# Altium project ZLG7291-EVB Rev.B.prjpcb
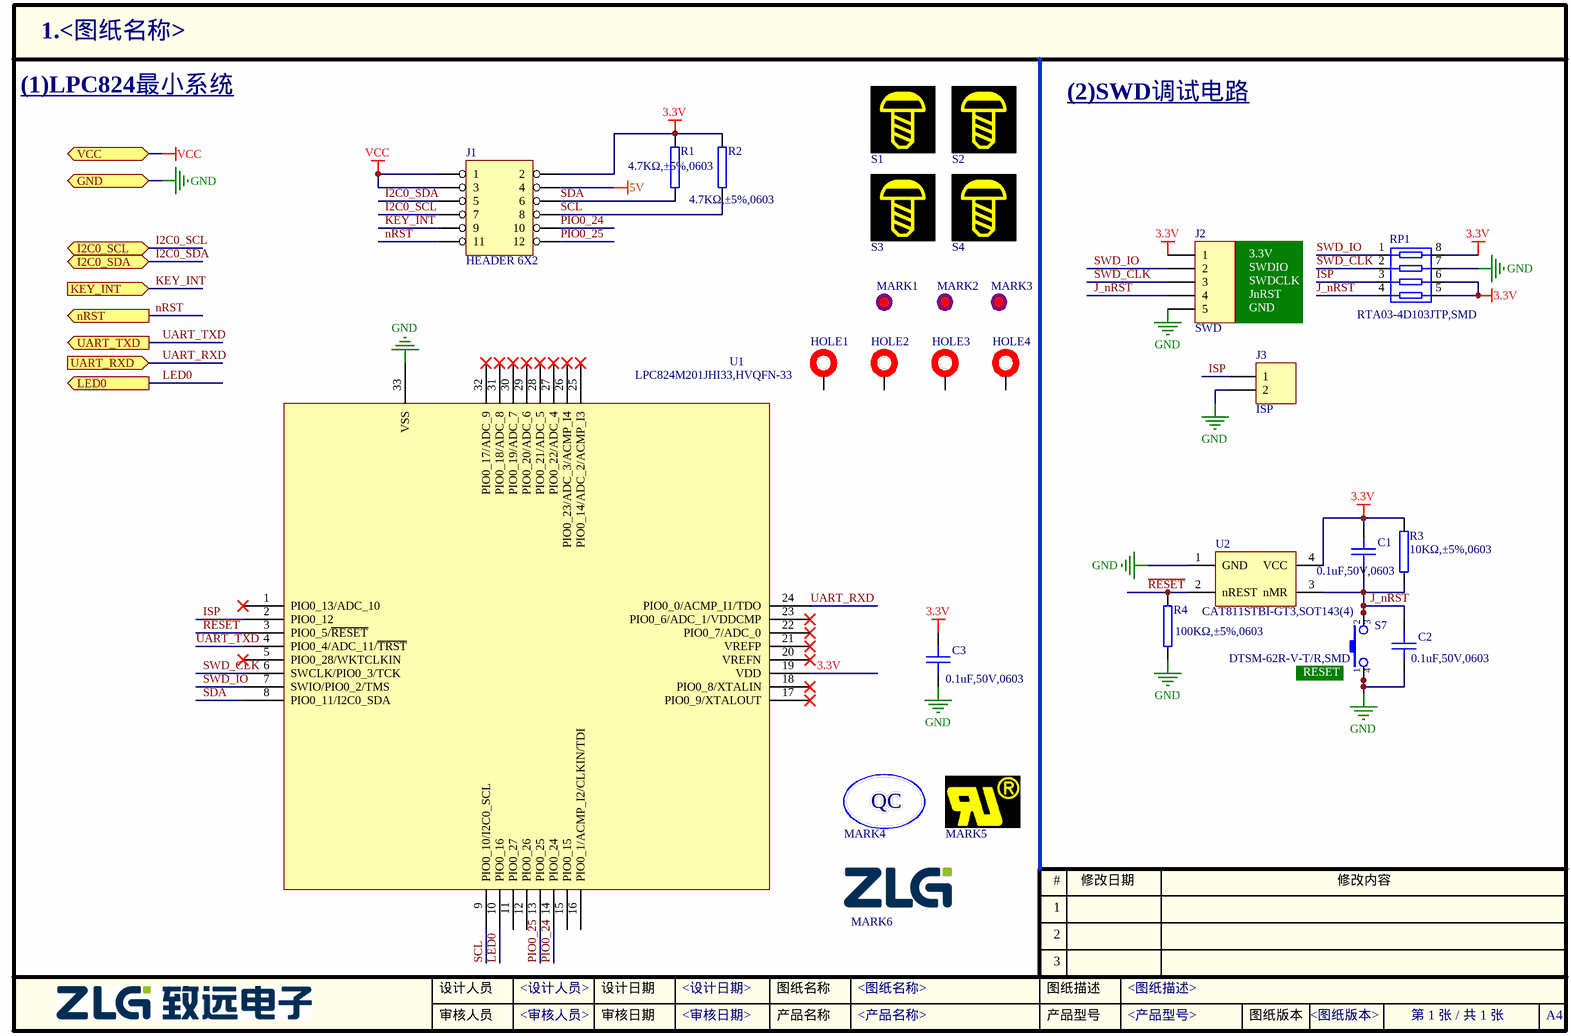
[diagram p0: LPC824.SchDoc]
3 sheets, 77 parts. Net scope: flat (ports and power ports of the same name join across sheets).
Board file: ZLG7291-EVB Rev.B.PCBDOC
Sheets:
  LPC824.SchDoc
  ZLG7291.SchDoc
  POWER.SchDoc

## Sheet LPC824.SchDoc
size A4; CheckedBy: <审核人员>; Author: <设计人员>; DocumentNumber: 1; SheetNumber: 1; SheetTotal: 1; PageSetup: Record=PageOptions|CenterHorizontal=True|CenterVertical=True|PrintScale=1.00|XCorrection=1.00|YCorrection=1.00|PrintKind=0|BorderSize=5000000|LeftOffset=0|BottomOffset=0|Orientation=2|PaperLength=1000|PaperWidth=1000|Scale=100|PaperSource=7|PrintQuality=600|MediaType=1|DitherType=10|PaperKind=A4|PrintScaleMode=1; DesignDate: <设计日期>; CheckDate: <审核日期>; SheetName: <图纸名称>; SheetVersion: <图纸版本>; SheetDescription: <图纸描述>; ProductName: <产品名称>; ProductModel: <产品型号>

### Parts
C1  0.1uF,50V,0603  [0603C]
C2  0.1uF,50V,0603  [0603C]
C3  0.1uF,50V,0603  [0603C]
HOLE1  HOLE - 不上螺丝  [HOLE-2.2]  (value not drawn)  (no BOM)
HOLE2  HOLE - 不上螺丝  [HOLE-2.2]  (value not drawn)  (no BOM)
HOLE3  HOLE - 不上螺丝  [HOLE-2.2]  (value not drawn)  (no BOM)
HOLE4  HOLE - 不上螺丝  [HOLE-2.2]  (value not drawn)  (no BOM)
J1  HEADER 6X2  [IDC-12-2.54]
J2  SWD  [SIP-5-2.54]
J3  ISP  [SIP-2-2.54]
MARK1  MARKER  [MARKER-C-1.0M]  (value not drawn)  (no BOM)
MARK2  MARKER  [MARKER-C-1.0M]  (value not drawn)  (no BOM)
MARK3  MARKER  [MARKER-C-1.0M]  (value not drawn)  (no BOM)
MARK4  ZY QC  [ZY_QC]  (value not drawn)  (no BOM)
MARK5  UR  [ZY_UR-3X2]  (value not drawn)  (no BOM)
MARK6  ZLGLOGO  [ZLG0.5]  (value not drawn)  (no BOM)
R1  4.7KΩ,±5%,0603  [0603R]
R2  4.7KΩ,±5%,0603  [0603R]
R3  10KΩ,±5%,0603  [0603R]
R4  100KΩ,±5%,0603  [0603R]
RP1  RTA03-4D103JTP,SMD  [0603RA]
S1  (no value)  [Screw-Mark2]  (no BOM)
S2  (no value)  [Screw-Mark2]  (no BOM)
S3  (no value)  [Screw-Mark2]  (no BOM)
S4  (no value)  [Screw-Mark2]  (no BOM)
S7  DTSM-62R-V-T/R,SMD  [KEY-6S]
U1  LPC824M201JHI33,HVQFN-33  [QFN50P500X500X85-33N]
U2  CAT811STBI-GT3,SOT143(4)  [SOT-143]

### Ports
GND, I2C0_SCL (bidir), I2C0_SDA (bidir), KEY_INT (in), LED0 (out), nRST (out), UART_RXD (in), UART_TXD (out), VCC

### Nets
3.3V: C1.1 C3.1 J1.2 J2.1 R1.2 R2.2 R3.2 RP1.5 RP1.6 RP1.8 U1.19(VDD) U2.4(VCC)
5V: J1.4
GND: C2.2 C3.2 J2.5 J3.2 R4.1 RP1.7 S7.1 S7.4 U1.33(VSS) U2.1(GND) ; port GND
VCC: J1.1 J1.3 ; port VCC
I2C0_SCL: J1.7 ; port I2C0_SCL
I2C0_SDA: J1.5 ; port I2C0_SDA
ISP: J3.1 RP1.3 U1.2(PIO0_12)
J_nRST: C1.2 C2.1 J2.4 R3.1 RP1.4 S7.2 S7.3 U2.3(nMR)
KEY_INT: J1.9 ; port KEY_INT
LED0: U1.10(PIO0_16) ; port LED0
nRST: J1.11 ; port nRST
PIO0_24: J1.10 U1.14(PIO0_24)
PIO0_25: J1.12 U1.13(PIO0_25)
~{RESET}: R4.2 U1.3(PIO0_5/~{RESET}) U2.2(nREST)
SCL: J1.8 R2.1 U1.9(PIO0_10/I2C0_SCL)
SDA: J1.6 R1.1 U1.8(PIO0_11/I2C0_SDA)
SWD_CLK: J2.3 RP1.2 U1.6(SWCLK/PIO0_3/TCK)
SWD_IO: J2.2 RP1.1 U1.7(SWIO/PIO0_2/TMS)
UART_RXD: U1.24(PIO0_0/ACMP_I1/TDO) ; port UART_RXD
UART_TXD: U1.4(PIO0_4/ADC_11/~{TRST}) ; port UART_TXD

Not connected (* = marked no-connect by the designer): HOLE1 1; HOLE2 1; HOLE3 1; HOLE4 1; MARK1 0; MARK2 0; MARK3 0; U1 1(PIO0_13/ADC_10)* 5(PIO0_28/WKTCLKIN)* 11(PIO0_27) 12(PIO0_26) 15(PIO0_15) 16(PIO0_1/ACMP_I2/CLKIN/TDI) 17(PIO0_9/XTALOUT)* 18(PIO0_8/XTALIN)* 20(VREFN)* 21(VREFP)* 22(PIO0_7/ADC_0)* 23(PIO0_6/ADC_1/VDDCMP)* 25(PIO0_14/ADC_2/ACMP_I3)* 26(PIO0_23/ADC_3/ACMP_I4)* 27(PIO0_22/ADC_4)* 28(PIO0_21/ADC_5)* 29(PIO0_20/ADC_6)* 30(PIO0_19/ADC_7)* 31(PIO0_18/ADC_8)* 32(PIO0_17/ADC_9)*

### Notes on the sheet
- (1)LPC824最小系统
- (2)SWD调试电路
- (near R2) SCL
- 3.3V
- SWDIO
- SWDCLK
- JnRST
- GND
- (near S7) RESET

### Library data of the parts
C1-C3 = 02.01.00015: C1608X7R1H104KT000N,0603,TDK,0.1uF,X7R,±10%,50V,; 旧物料代码: 1.02.01.0072; 名称: 电容; 封装: 0603; 贴片和直插: SMT; 环保状态: RoHS2.0+REACH; PCB备注: 151110lmd; 器件优选方案: 推荐使用; 生产单位: PCS
J2 = Header 5H: Header, 5-Pin, Right Angle
J3 = Header 2H: Header, 2-Pin, Right Angle
MARK6 = ZLGLOGO: ZLGLIB
R1 R2 = 01.01.00005: RTT03472JTP,0603,RALEC,4.7KΩ,±5%,1/10W,; 旧物料代码: 1.01.01.0045; 名称: 电阻; 封装: 0603; 贴片和直插: SMT; 环保状态: RoHS2.0+REACH; 器件优选方案: 通用物料; 生产单位: PCS
R3 = 01.01.00002: RTT03103JTP,0603,RALEC,10KΩ,±5%,1/10W,; 旧物料代码: 1.01.01.0051; 名称: 电阻; 封装: 0603; 贴片和直插: SMT; 环保状态: RoHS2.0+REACH; 器件优选方案: 通用物料; 生产单位: PCS
R4 = 01.01.00031: RTT03104JTP,0603,RALEC,100KΩ,±5%,1/10W,; 旧物料代码: 1.01.01.0062; 名称: 电阻; 封装: 0603; 贴片和直插: SMT; 环保状态: RoHS2.0+REACH; 器件优选方案: 通用物料; 生产单位: PCS
RP1 = 01.02.00003: RTA03-4D103JTP,SMD,RALEC,10KΩ*4,; 旧物料代码: 1.01.04.0004; 名称: 网络电阻; 封装: 0603*4; 贴片和直插: SMT; 环保状态: RoHS2.0+REACH; 器件优选方案: 通用物料; 生产单位: PCS
S1-S4 = Screw-Mark
S7 = 17.01.00031: DTSM-62R-V-T/R,SMD,DIP,红色,6.2*6.2*5mm,圆达; 旧物料代码: 1.09.01.0004; 名称: 开关; 封装: SMT; 环保状态: RoHS2.0; 器件优选方案: 通用物料; 生产单位: PCS
U1 = 08.01.02201: LPC824M201JHI33,HVQFN-33,NXP,; 旧物料代码: 1.05.01.0105; 名称: 集成电路; 贴片和直插: SMT; 环保状态: RoHS2.0+REACH; PCB备注: 151130mxz160506ZW; 器件优选方案: 核心物料; 生产单位: PCS
U2 = 08.09.01426: CAT811STBI-GT3,SOT143(4),ON,; 旧物料代码: 1.05.07.0023; 名称: 集成电路; 贴片和直插: SMT; 环保状态: RoHS2.0+REACH; 器件优选方案: 通用物料; 生产单位: PCS

## Sheet ZLG7291.SchDoc
size A4; CheckedBy: <审核人员>; Author: <设计人员>; DocumentNumber: 1; SheetNumber: 1; SheetTotal: 1; PageSetup: Record=PageOptions|CenterHorizontal=True|CenterVertical=True|PrintScale=1.00|XCorrection=1.00|YCorrection=1.00|PrintKind=0|BorderSize=5000000|LeftOffset=0|BottomOffset=0|Orientation=2|PaperLength=1000|PaperWidth=1000|Scale=100|PaperSource=7|PrintQuality=600|MediaType=1|DitherType=10|PaperKind=A4|PrintScaleMode=1; DesignDate: <设计日期>; CheckDate: <审核日期>; SheetName: <图纸名称>; SheetVersion: <图纸版本>; SheetDescription: <图纸描述>; ProductName: <产品名称>; ProductModel: <产品型号>
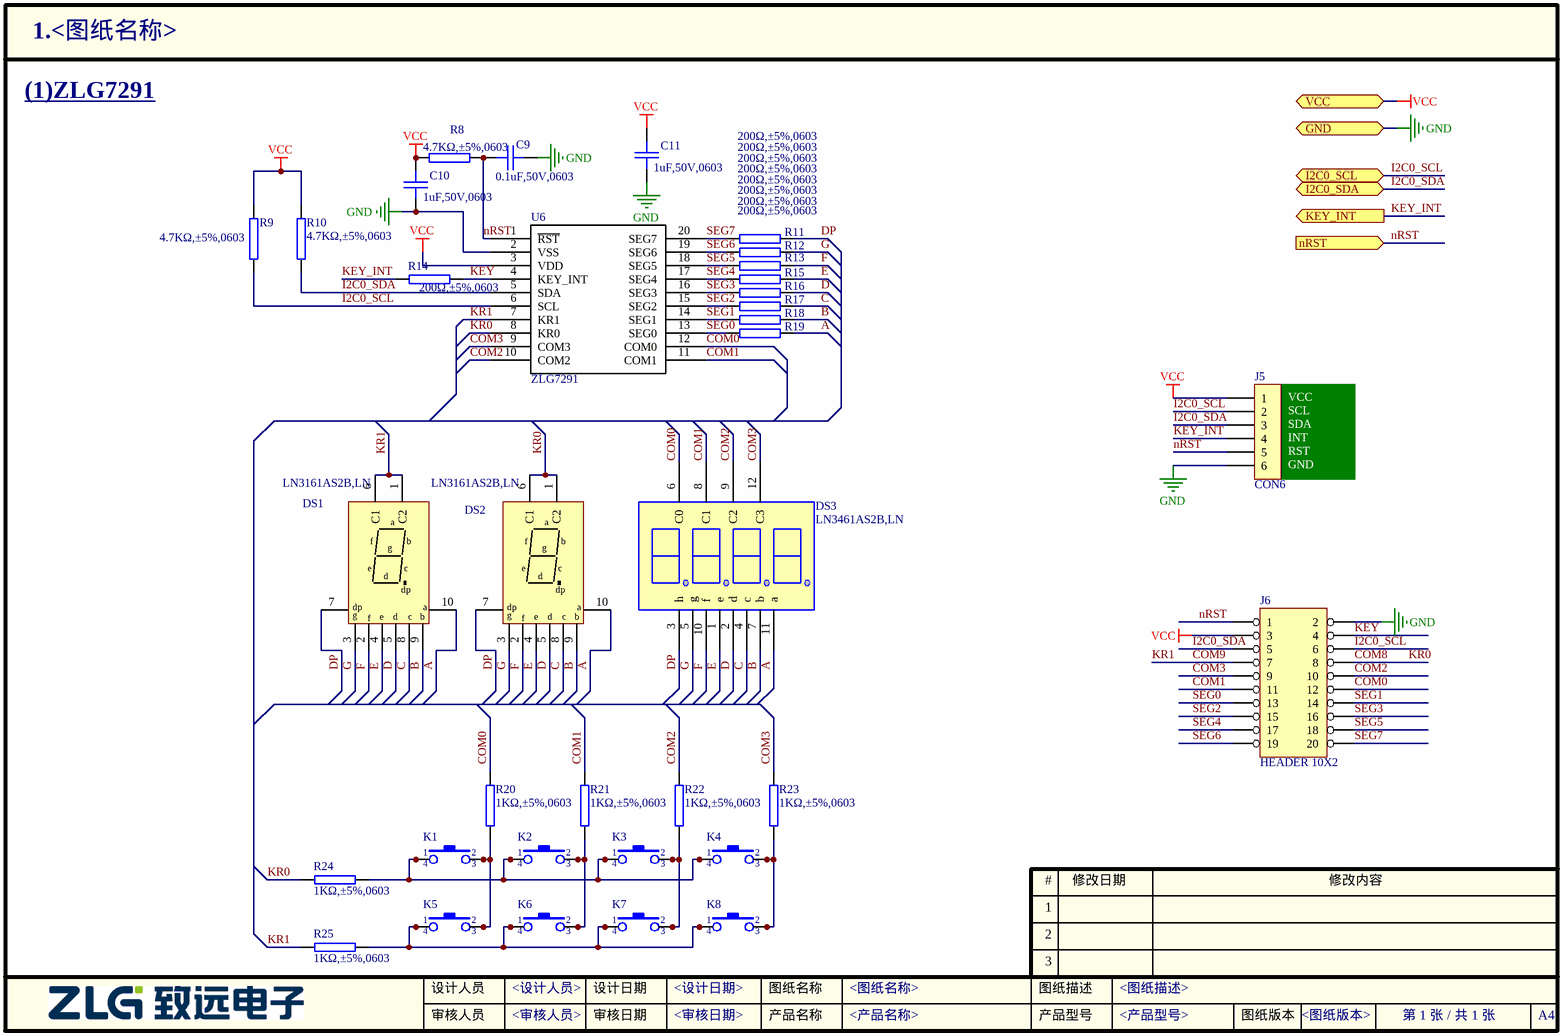
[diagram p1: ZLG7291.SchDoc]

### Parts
C9  0.1uF,50V,0603  [0603C]
C10  1uF,50V,0603  [0603C]
C11  1uF,50V,0603  [0603C]
DS1  LN3161AS2B,LN  [LN3161]
DS2  LN3161AS2B,LN  [LN3161]
DS3  LN3461AS2B,LN  [LN3461-3000X1400X720]
J5  CON6  [SIP-6-2.54]
J6  HEADER 10X2  [TEST-TSSOP20]
K1  TS0641-0501B,SMD  [KEY-6S]  (value not drawn)
K2  TS0641-0501B,SMD  [KEY-6S]  (value not drawn)
K3  TS0641-0501B,SMD  [KEY-6S]  (value not drawn)
K4  TS0641-0501B,SMD  [KEY-6S]  (value not drawn)
K5  TS0641-0501B,SMD  [KEY-6S]  (value not drawn)
K6  TS0641-0501B,SMD  [KEY-6S]  (value not drawn)
K7  TS0641-0501B,SMD  [KEY-6S]  (value not drawn)
K8  TS0641-0501B,SMD  [KEY-6S]  (value not drawn)
R8  4.7KΩ,±5%,0603  [0603R]
R9  4.7KΩ,±5%,0603  [0603R]
R10  4.7KΩ,±5%,0603  [0603R]
R11  200Ω,±5%,0603  [0603R]
R12  200Ω,±5%,0603  [0603R]
R13  200Ω,±5%,0603  [0603R]
R14  200Ω,±5%,0603  [0603R]
R15  200Ω,±5%,0603  [0603R]
R16  200Ω,±5%,0603  [0603R]
R17  200Ω,±5%,0603  [0603R]
R18  200Ω,±5%,0603  [0603R]
R19  200Ω,±5%,0603  [0603R]
R20  1KΩ,±5%,0603  [0603R]
R21  1KΩ,±5%,0603  [0603R]
R22  1KΩ,±5%,0603  [0603R]
R23  1KΩ,±5%,0603  [0603R]
R24  1KΩ,±5%,0603  [0603R]
R25  1KΩ,±5%,0603  [0603R]
U6  ZLG7291  [TSOP65P640X120-20N]

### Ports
GND, I2C0_SCL (bidir), I2C0_SDA (bidir), KEY_INT (out), nRST (in), VCC

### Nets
GND: C9.2 C10.2 C11.2 J5.6 J6.2 U6.2(VSS) ; port GND
VCC: C10.1 C11.1 J5.1 J6.3 R8.2 R9.2 R10.2 U6.3(VDD) ; port VCC
A: DS1.10(a) DS2.10(a) DS3.11(a) R19.2
B: DS1.9(b) DS2.9(b) DS3.7(b) R18.2
C: DS1.8(c) DS2.8(c) DS3.4(c) R17.2
COM0: DS3.6(C0) J6.12 R20.2 U6.12(COM0)
COM1: DS3.8(C1) J6.11 R21.2 U6.11(COM1)
COM2: DS3.9(C2) J6.10 R22.2 U6.10(COM2)
COM3: DS3.12(C3) J6.9 R23.2 U6.9(COM3)
COM8: DS2.1(C2) DS2.6(C1) J6.8 R24.2 U6.8(KR0)  [also labelled KR0]
COM9: DS1.1(C2) DS1.6(C1) J6.7 R25.2 U6.7(KR1)  [also labelled KR1]
D: DS1.5(d) DS2.5(d) DS3.2(d) R16.2
DP: DS1.7(dp) DS2.7(dp) DS3.3(h) R11.2
E: DS1.4(e) DS2.4(e) DS3.1(e) R15.2
F: DS1.2(f) DS2.2(f) DS3.10(f) R13.2
G: DS1.3(g) DS2.3(g) DS3.5(g) R12.2
I2C0_SCL: J5.2 J6.6 R9.1 U6.6(SCL) ; port I2C0_SCL
I2C0_SDA: J5.3 J6.5 R10.1 U6.5(SDA) ; port I2C0_SDA
KEY: J6.4 R14.2 U6.4(KEY_INT)
KEY_INT: J5.4 R14.1 ; port KEY_INT
nRST: C9.1 J5.5 J6.1 R8.1 U6.1(~{RST}) ; port nRST
SEG0: J6.13 R19.1 U6.13(SEG0)
SEG1: J6.14 R18.1 U6.14(SEG1)
SEG2: J6.15 R17.1 U6.15(SEG2)
SEG3: J6.16 R16.1 U6.16(SEG3)
SEG4: J6.17 R15.1 U6.17(SEG4)
SEG5: J6.18 R13.1 U6.18(SEG5)
SEG6: J6.19 R12.1 U6.19(SEG6)
SEG7: J6.20 R11.1 U6.20(SEG7)
NetK1_1: K1.1 K1.4 K2.1 K2.4 K3.1 K3.4 K4.1 K4.4 R24.1
NetK1_2: K1.2 K1.3 K5.2 K5.3 R20.1
NetK2_2: K2.2 K2.3 K6.2 K6.3 R21.1
NetK3_2: K3.2 K3.3 K7.2 K7.3 R22.1
NetK4_2: K4.2 K4.3 K8.2 K8.3 R23.1
NetK5_1: K5.1 K5.4 K6.1 K6.4 K7.1 K7.4 K8.1 K8.4 R25.1

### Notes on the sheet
- (1)ZLG7291
- (near J5) SCL
- (near J5) SDA
- (near J5) INT
- (near J5) VCC
- (near J5) RST
- (near J5) GND

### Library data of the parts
C9 = 02.01.00015: as C1 on sheet LPC824
C10 C11 = 02.01.00497: C1608X5R1H105K080AB,0603,TDK,1uF,X5R,±10%,50V; 名称: 电容; 封装: 0603; 贴片和直插: SMT; 环保状态: RoHS2.0; PCB备注: 200226FHX; 器件优选方案: 通用物料; 生产单位: PCS
DS1 DS2 = LN3161: LN3161AS2B,LN,A/1,14*7.5*8.5mm,; 物料代码: 16.03.00010; 旧物料代码: 1.08.01.0012; 名称: 数码管; 封装: THT; 环保状态: RoHS2.0; PCB备注: 160825ZW; 器件优选方案: 不推荐使用; 生产单位: PCS
DS3 = 16.03.00006: LN3461AS2B,LN,A/1,30*14*7.3mm,; 旧物料代码: 1.08.01.0003; 名称: 数码管; 封装: THT; 环保状态: RoHS2.0; PCB备注: 焊盘孔径改为0.8mm，外形丝印改变，两排焊盘间间距改为10.36，Fwrj-Shcj-Tlq-141224; 器件优选方案: 不推荐使用; 生产单位: PCS
J5 = CON6: Connector
K1-K8 = 17.01.00005: TS0641-0501B,SMD,DAILYLON,黑色,卷带装,6*6*5.0mm,; 旧物料代码: 1.09.01.0003; 名称: 轻触开关; 封装: SMT; 环保状态: RoHS2.0; 器件优选方案: 通用物料; 生产单位: PCS
R8-R10 = 01.01.00005: as R1 on sheet LPC824
R11-R19 = 01.01.00202: RTT03201JTP,0603,RALEC,200Ω,±5%,1/10W,; 旧物料代码: 1.01.01.0026; 名称: 电阻; 封装: 0603; 贴片和直插: SMT; 环保状态: RoHS2.0+REACH; 器件优选方案: 通用物料; 生产单位: PCS
R20-R25 = 01.01.00012: RTT03102JTP,0603,RALEC,1KΩ,±5%,1/10W,; 旧物料代码: 1.01.01.0035; 名称: 电阻; 封装: 0603; 贴片和直插: SMT; 环保状态: RoHS2.0+REACH; 器件优选方案: 通用物料; 生产单位: PCS

## Sheet POWER.SchDoc
size A4; CheckedBy: <审核人员>; Author: <设计人员>; DocumentNumber: 1; SheetNumber: 1; SheetTotal: 1; PageSetup: Record=PageOptions|CenterHorizontal=True|CenterVertical=True|PrintScale=1.00|XCorrection=1.00|YCorrection=1.00|PrintKind=0|BorderSize=5000000|LeftOffset=0|BottomOffset=0|Orientation=2|PaperLength=1000|PaperWidth=1000|Scale=100|PaperSource=7|PrintQuality=600|MediaType=1|DitherType=10|PaperKind=A4|PrintScaleMode=1; DesignDate: <设计日期>; CheckDate: <审核日期>; SheetName: <图纸名称>; SheetVersion: <图纸版本>; SheetDescription: <图纸描述>; ProductName: <产品名称>; ProductModel: <产品型号>
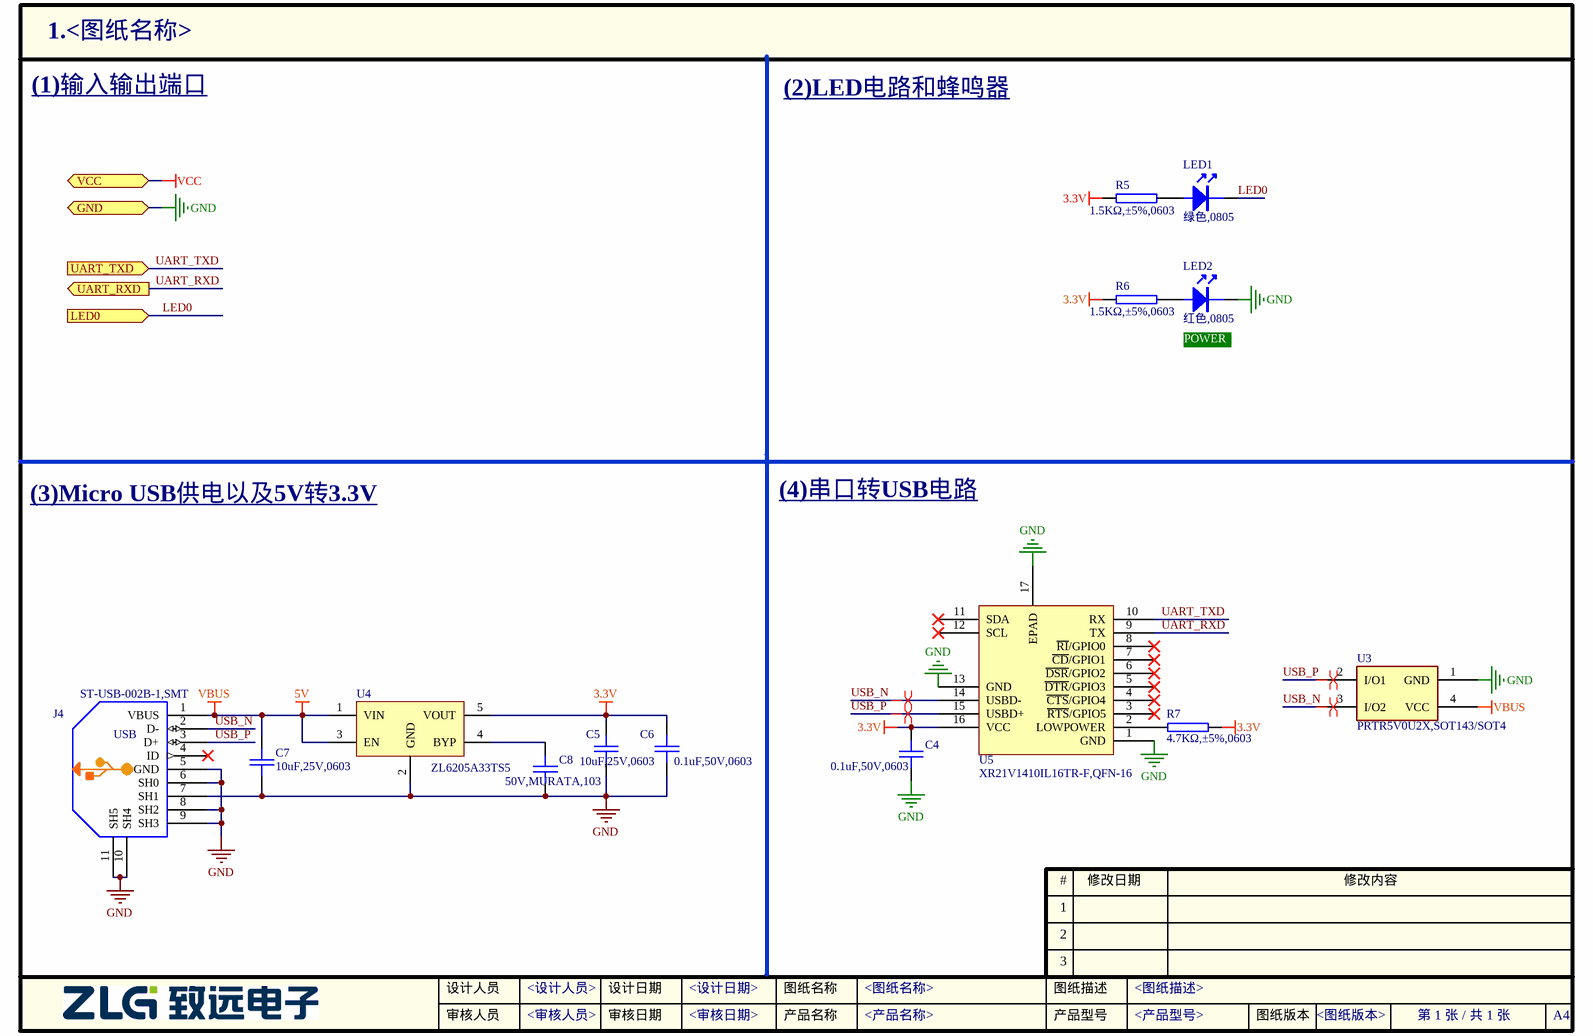
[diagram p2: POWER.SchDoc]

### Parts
C4  0.1uF,50V,0603  [0603C]
C5  10uF,25V,0603  [0603C]
C6  0.1uF,50V,0603  [0603C]
C7  10uF,25V,0603  [0603C]
C8  50V,MURATA,103  [0603C]
J4  ST-USB-002B-1,SMT  [MICROUSB-ST-USB-002B-1]
LED1  绿色,0805  [LED-0805]
LED2  红色,0805  [LED-0805]
R5  1.5KΩ,±5%,0603  [0603R]
R6  1.5KΩ,±5%,0603  [0603R]
R7  4.7KΩ,±5%,0603  [0603R]
U3  PRTR5V0U2X,SOT143/SOT4  [sot-143]
U4  ZL6205A33TS5  [SOT-23-5]
U5  XR21V1410IL16TR-F,QFN-16  [QFN50P300X300X80-17AN]

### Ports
GND, LED0 (in), UART_RXD (out), UART_TXD (in), VCC

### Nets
3.3V: C4.1 C5.1 C6.1 R5.1 R6.1 R7.2 U4.5(VOUT) U5.16(VCC)
5V: C7.1 J4.1(VBUS) U3.4(VCC) U4.1(VIN) U4.3(EN)  [also labelled VBUS]
GND: C4.2 C5.2 C6.2 C7.2 C8.2 J4.5(GND) J4.6(SH0) J4.7(SH1) J4.8(SH2) J4.9(SH3) J4.10(SH4) J4.11(SH5) LED2.2 U3.1(GND) U4.2(GND) U5.1(GND) U5.13(GND) U5.17(EPAD) ; port GND
LED0: LED1.2 ; port LED0
UART_RXD: U5.9(TX) ; port UART_RXD
UART_TXD: U5.10(RX) ; port UART_TXD
USB_N: J4.2(D-) U3.3(I/O2) U5.14(USBD-)
USB_P: J4.3(D+) U3.2(I/O1) U5.15(USBD+)
NetC8_1: C8.1 U4.4(BYP)
NetLED1_1: LED1.1 R5.2
NetLED2_1: LED2.1 R6.2
NetR7_1: R7.1 U5.2(LOWPOWER)

Not connected (* = marked no-connect by the designer): J4 4(ID)*; U5 3(~{RTS}/GPIO5)* 4(~{CTS}/GPIO4)* 5(~{DTR}/GPIO3)* 6(~{DSR}/GPIO2)* 7(~{CD}/GPIO1)* 8(~{RI}/GPIO0)* 11(SDA)* 12(SCL)*

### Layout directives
differential pair: USB_N, USB_P

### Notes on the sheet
- (1)输入输出端口
- (2)LED电路和蜂鸣器
- RESET
- POWER
- (3)Micro USB供电以及5V转3.3V
- (4)串口转USB电路

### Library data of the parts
C4 = 02.01.00015: as C1 on sheet LPC824
C5 C7 = 02.01.00543: GRM188R61E106MA73D,0603,MURATA,10uF,X5R,±20%,25V; 名称: 电容; 封装: 0603; 贴片和直插: SMT; 环保状态: RoHS2.0; PCB备注: 210113ZW; 器件优选方案: 通用物料; 生产单位: PCS
C6 = 02.01.00015: C1608X7R1H104KT000N,0603,TDK,0.1uF,X7R,±10%,50V,; 旧物料代码: 1.02.01.0072; 名称: 电容; 封装: 0603; 贴片和直插: SMT; PCB备注: 151110lmd; 器件优选方案: 推荐使用
C8 = 02.01.00364: GCM188R71H103KA15D,103,±10%,50V,X7R,0603,MURATA,; 旧物料代码: 1.02.01.0090; 名称: 电容; 封装: 0603; 贴片和直插: SMT; 环保状态: RoHS2.0+REACH; PCB备注: 180305ZW; 器件优选方案: 不推荐使用; 生产单位: PCS
J4 = 20.02.00033: ST-USB-002B-1,SMT,SUNGTECH,MicroUSB-A; 名称: 连接器; 环保状态: RoHS2.0; PCB备注: 190710lmd; 器件优选方案: 通用物料; 生产单位: PCS
LED1 = 04.04.00006: 0805QBGC-G,SMD,BRIGHT,翠绿色,; 旧物料代码: 1.04.05.0015; 名称: 发光二极管; 封装: 0805; 贴片和直插: SMT; 环保状态: RoHS2.0; 器件优选方案: 通用物料; 生产单位: PCS
LED2 = 04.04.00010: 0805QRC,SMD,BRIGHT,红色,; 旧物料代码: 1.04.05.0001; 名称: 发光二极管; 封装: 0805; 贴片和直插: SMT; 环保状态: RoHS2.0; 器件优选方案: 通用物料; 生产单位: PCS
R5 R6 = 01.01.00039: RTT03152JTP,0603,RALEC,1.5KΩ,±5%,1/10W,; 旧物料代码: 1.01.01.0037; 名称: 电阻; 封装: 0603; 贴片和直插: SMT; 环保状态: RoHS2.0+REACH; 器件优选方案: 通用物料; 生产单位: PCS
R7 = 01.01.00005: as R1 on sheet LPC824
U3 = 09.04.00190: PRTR5V0U2X,SOT143/SOT4,NEXPERIA,; 旧物料代码: 1.05.10.0153; 名称: 二极管; 贴片和直插: SMT; 环保状态: RoHS2.0+REACH; 器件优选方案: 通用物料; 生产单位: PCS
U4 = 89.12.00013: 名称: 集成电路; 封装: TSOT-23-5; 厂商: ZLG; 贴片和直插: SMT; PCB备注: 191105CZY; 器件优选方案: 通用物料
U5 = 08.08.00611: XR21V1410IL16TR-F,QFN-16,EXAR,; 旧物料代码: 1.05.08.0043; 名称: 集成电路; 贴片和直插: SMT; 环保状态: RoHS2.0+REACH; PCB备注: 170621ZW; 器件优选方案: 不推荐使用; 生产单位: PCS

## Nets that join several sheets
3.3V: LPC824 (12 pins), POWER (8 pins)
5V: LPC824 (J1.4), POWER (5 pins)
GND: LPC824 (10 pins), ZLG7291 (6 pins), POWER (18 pins)
VCC: LPC824 (J1.1 J1.3), ZLG7291 (8 pins)
I2C0_SCL: LPC824 (J1.7), ZLG7291 (J5.2 J6.6 R9.1 U6.6)
I2C0_SDA: LPC824 (J1.5), ZLG7291 (J5.3 J6.5 R10.1 U6.5)
KEY_INT: LPC824 (J1.9), ZLG7291 (J5.4 R14.1)
LED0: LPC824 (U1.10), POWER (LED1.2)
nRST: LPC824 (J1.11), ZLG7291 (5 pins)
UART_RXD: LPC824 (U1.24), POWER (U5.9)
UART_TXD: LPC824 (U1.4), POWER (U5.10)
